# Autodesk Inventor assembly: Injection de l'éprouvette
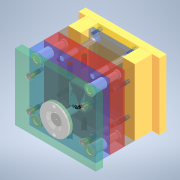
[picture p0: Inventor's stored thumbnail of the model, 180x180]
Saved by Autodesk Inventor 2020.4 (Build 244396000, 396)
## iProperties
Created: 2021-10
Part Number: Injection de l'éprouvette
Document SubType Name: Assembly
Designer: mel
Author: mel
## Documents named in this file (6)
- D:\travail\année 2020-2021\itec\prépa injection plastique eduscol\dossier de travail\Ensemble des pièces de l'activité\Conception de moule1\Injection de l'éprouvette.iam
- D:\travail\année 2020-2021\itec\prépa injection plastique eduscol\dossier de travail\Ensemble des pièces de l'activité\Conception de moule1\Injection de l'éprouvette_éprouvette_LY.iam
- D:\travail\année 2020-2021\itec\prépa injection plastique eduscol\dossier de travail\Ensemble des pièces de l'activité\Conception de moule1\Injection de l'éprouvette_RG.ipt
- D:\travail\année 2020-2021\itec\prépa injection plastique eduscol\dossier de travail\Ensemble des pièces de l'activité\Conception de moule1\Bague de centrage\LKM_LR\Injection de l'éprouvette_LR-100-36.ipt
- D:\travail\année 2020-2021\itec\prépa injection plastique eduscol\dossier de travail\Ensemble des pièces de l'activité\Conception de moule1\Mo\FUTABA_SA-S 3\Injection de l'éprouvette_MB.iam
- D:\travail\année 2020-2021\itec\prépa injection plastique eduscol\dossier de travail\Ensemble des pièces de l'activité\Conception de moule1\Buse d'injection\HASCO_Z51\Injection de l'éprouvette_Z51-18x56-3,5_1.ipt
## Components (5 placed, 5 different names)
1. Injection de l'éprouvette_éprouvette_LY:1 [sub-assembly] — Affleurement:1, Affleurement:2, Affleurement:3, Affleurement:12, Affleurement:13
2. Injection de l'éprouvette_RG:1 — Affleurement:4, Affleurement:5, Affleurement:6, Affleurement:8, Placage:3
3. Injection de l'éprouvette_MB:1 [sub-assembly] — Placage:1, Angle:1, Placage:2, Placage:4, Affleurement:13
4. Injection de l'éprouvette_Z51-18x56-3,5_1:1 — Placage:2, Placage:3, Placage:5
5. Injection de l'éprouvette_LR-100-36:1 — Placage:4, Placage:5
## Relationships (15: Flush 9, Mate 5, Angle 1)
- Affleurement:1 [Flush]: Injection de l'éprouvette_éprouvette_LY:1
- Affleurement:2 [Flush]: Injection de l'éprouvette_éprouvette_LY:1
- Affleurement:3 [Flush]: Injection de l'éprouvette_éprouvette_LY:1
- Affleurement:4 [Flush]: Injection de l'éprouvette_RG:1
- Affleurement:5 [Flush]: Injection de l'éprouvette_RG:1
- Affleurement:6 [Flush]: Injection de l'éprouvette_RG:1
- Affleurement:8 [Flush]: Injection de l'éprouvette_RG:1
- Placage:1 [Mate]: Injection de l'éprouvette_MB:1
- Angle:1: Injection de l'éprouvette_MB:1
- Placage:2 [Mate]: Injection de l'éprouvette_MB:1 ↔ Injection de l'éprouvette_Z51-18x56-3,5_1:1
- Placage:3 [Mate]: Injection de l'éprouvette_RG:1 ↔ Injection de l'éprouvette_Z51-18x56-3,5_1:1
- Placage:4 [Mate]: Injection de l'éprouvette_MB:1 ↔ Injection de l'éprouvette_LR-100-36:1
- Placage:5 [Mate]: Injection de l'éprouvette_Z51-18x56-3,5_1:1 ↔ Injection de l'éprouvette_LR-100-36:1
- Affleurement:12 [Flush]: Injection de l'éprouvette_éprouvette_LY:1
- Affleurement:13 [Flush]: Injection de l'éprouvette_éprouvette_LY:1 ↔ Injection de l'éprouvette_MB:1
